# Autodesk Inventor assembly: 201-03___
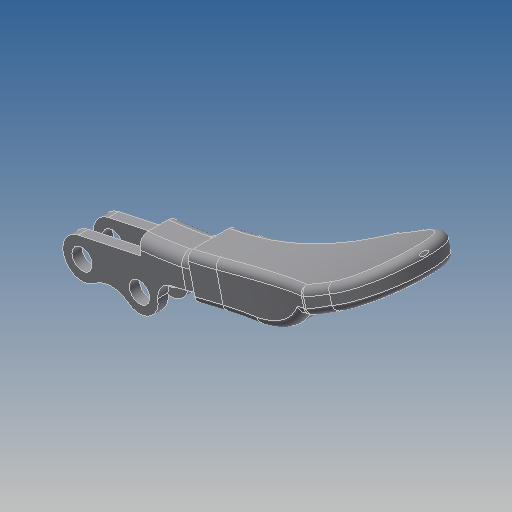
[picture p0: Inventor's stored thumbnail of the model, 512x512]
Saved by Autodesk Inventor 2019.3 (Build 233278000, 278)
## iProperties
Created: 2010-06
Part Number: 201-03___
Material: Ogólny
Document SubType Name: Assembly
Designer: CADENGINEERING4
Author: CADENGINEERING4
Revision Number: ANY
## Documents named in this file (3)
- E:\STRONA\Horizontal toggle clamp\CH-201-AR\201-03___.iam
- E:\STRONA\Horizontal toggle clamp\CH-201-AR\201-A-03___.ipt
- E:\STRONA\Horizontal toggle clamp\CH-201-AR\201-05___.ipt
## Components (2 placed, 2 different names)
1. 201-A-03_??_13
2. 201-05_??_14
